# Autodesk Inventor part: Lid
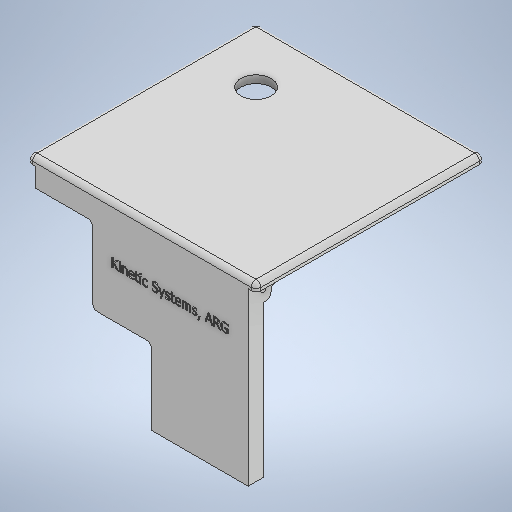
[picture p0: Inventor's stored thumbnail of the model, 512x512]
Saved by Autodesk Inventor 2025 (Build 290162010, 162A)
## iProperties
Created: 2023-12
Part Number: Lid
Material: Generic
Document SubType Name: Modeling
Designer: Andrew
Density: 1 g/cm^3
Appearance: Default
Author: Andrew
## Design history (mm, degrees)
sketch "Sketch1"
  geometry: L1 (76.2, 76.2)-(-76.2, 76.2); L2 (-76.2, 76.2)-(-76.2, -76.2); L3 (-76.2, -76.2)-(76.2, -76.2); L4 (76.2, -76.2)-(76.2, 76.2); 1 further point
  constraints: 8 end point, 2 parallel, 1 horizontal, 1 perpendicular
  dimensions: "d0" = 152.4 distance between parallel lines of L3 L1 (= d1); "d1" = 152.4 distance between parallel lines of L2 L4; "d2" = 76.2 distance from line of point (0, 0) L4 (= 0.5 x d1); "d3" = 76.2 distance from line of L3 point (0, 0) (= 0.5 x d1)
extrude "Extrusion1" new body sketch "Sketch1" distance "d4" = 5.08; taper "d5" = 0 deg
sketch "Sketch3"
  geometry: L1 (-76.2, 76.2)-(76.2, 76.2) reference; L2 (-70.993, 76.2)-(70.993, 76.2); L3 (70.993, 76.2)-(70.993, 71.12); L4 (70.993, 71.12)-(-70.993, 71.12); L5 (-70.993, 71.12)-(-70.993, 76.2); L6 (-76.2, -76.2)-(-76.2, 76.2) reference; L7 (76.2, 76.2)-(76.2, -76.2) reference; 2 further points
  constraints: 8 end point, 2 parallel, 1 horizontal, 1 perpendicular, 1 point on line
  dimensions: "d6" = 5.08 distance between parallel lines of L4 L1; "d7" = 5.207 distance between parallel lines of L6 L5; "d8" = 5.207 distance between parallel lines of L7 L3
extrude "Extrusion2" join sketch "Sketch3" distance "d9" = 76.2; taper "d10" = 0 deg
sketch "Sketch4"
  geometry: L1 (5.207, -5.08)-(5.207, -81.28) reference; L2 (5.207, -17.78)-(43.307, -17.78); L3 (43.307, -17.78)-(43.307, -81.28); L4 (43.307, -81.28)-(5.207, -81.28); L5 (5.207, -81.28)-(5.207, -17.78); L6 (147.193, -81.28)-(5.207, -81.28) reference; 2 further points
  constraints: 8 end point, 2 parallel, 1 horizontal, 1 perpendicular, 1 point on line
  dimensions: "d11" = 38.1 distance between parallel lines of L1 L3; "d12" = 63.5 distance between parallel lines of L4 L2; "d13" = 0 distance between parallel lines of L6 L4
extrude "Extrusion3" cut sketch "Sketch4" distance "d14" = 76.2; taper "d15" = 0 deg
sketch "Sketch5"
  geometry: L1 (-70.993, -70.993)-(70.993, -70.993); L2 (70.993, -70.993)-(70.993, -65.913); L3 (70.993, -65.913)-(-70.993, -65.913); L4 (-70.993, -65.913)-(-70.993, -70.993); L5 (70.993, -65.913)-(65.913, -65.913); L6 (65.913, -65.913)-(65.913, 71.12); L7 (65.913, 71.12)-(70.993, 71.12); L8 (70.993, 71.12)-(70.993, -65.913); L9 (-70.993, -65.913)-(-65.913, -65.913); L10 (-65.913, -65.913)-(-65.913, 71.12); L11 (-65.913, 71.12)-(-70.993, 71.12); L12 (-70.993, 71.12)-(-70.993, -65.913); L13 (76.2, -76.2)-(-76.2, -76.2) reference; L14 (-76.2, -76.2)-(-76.2, 76.2) reference; L15 (76.2, 76.2)-(76.2, -76.2) reference; L16 (70.993, 71.12)-(-70.993, 71.12) reference; 3 further points
  constraints: 24 end point, 6 parallel, 3 horizontal, 3 perpendicular, 1 point on line
  dimensions: "d16" = 5.08 distance between parallel lines of L1 L3; "d19" = 5.207 distance between parallel lines of L13 L1; "d20" = 5.207 distance between parallel lines of L14 L12 (= d19); "d21" = 5.207 distance between parallel lines of L15 L8 (= d19); "d22" = 5.08 distance between parallel lines of L8 L6 (= d16); "d23" = 5.08 distance between parallel lines of L10 L12 (= d16); "d24" = 0 distance between parallel lines of L16 L11
extrude "Extrusion4" join sketch "Sketch5" distance "d25" = 5.08; taper "d26" = 0 deg
sketch "Sketch6"
  geometry: L1 (5.08, 71.12)-(0, 71.12); L2 (0, 71.12)-(0, 0); L3 (0, 0)-(5.08, 0); L4 (5.08, 0)-(5.08, 71.12); L5 (136.906, 71.12)-(141.986, 71.12); L6 (141.986, 71.12)-(141.986, 63.5); L7 (141.986, 63.5)-(136.906, 63.5); L8 (136.906, 63.5)-(136.906, 71.12); L9 (103.886, 63.5)-(141.986, 63.5) reference; L10 (103.886, 0)-(0, 0) reference; 2 further points
  constraints: 16 end point, 4 parallel, 2 horizontal, 2 perpendicular, 1 midpoint
  dimensions: "d27" = 5.08 distance between parallel lines of L4 L2; "d28" = 5.08 distance between parallel lines of L6 L8; "d29" = 0 distance from line of L9 point (139.446, 63.5); "d30" = 0 distance between parallel lines of L10 L3
extrude "Extrusion5" join sketch "Sketch6" distance "d31" = 5.08; taper "d32" = 0 deg
fillet "Fillet1" dims "d33" = 3.175
fillet "Fillet9" dims "d140" = 6.35
sketch "Sketch7"
  geometry: L1 (-55.753, 60.96)-(-65.913, 60.96); L2 (-65.913, 60.96)-(-65.913, 71.12); L3 (-65.913, 71.12)-(-55.753, 71.12); L4 (-55.753, 71.12)-(-55.753, 60.96); L5 (55.753, 60.96)-(65.913, 60.96); L6 (65.913, 60.96)-(65.913, 71.12); L7 (65.913, 71.12)-(55.753, 71.12); L8 (55.753, 71.12)-(55.753, 60.96); L9 (-65.913, -62.738)-(-65.913, 62.865) reference; L10 (-36.068, 71.12)-(-62.738, 71.12) reference; L11 (65.913, 62.865)-(65.913, -62.738) reference; 2 further points
  constraints: 16 end point, 4 parallel, 2 horizontal, 2 perpendicular, 1 midpoint, 1 point on line
  dimensions: "d34" = 10.16 distance between parallel lines of L4 L2; "d35" = 10.16 distance between parallel lines of L1 L3; "d36" = 10.16 distance between parallel lines of L5 L7; "d37" = 10.16 distance from line of L6 point (55.753, 66.04); "d38" = 0 distance between parallel lines of L9 L2; "d39" = 0 distance between parallel lines of L10 L3; "d40" = 0 distance between parallel lines of L11 L6
extrude "Extrusion6" join sketch "Sketch7" distance "d41" = 12.7; taper "d42" = 0 deg
sketch "Sketch9"
  geometry: L1 (62.738, 60.96)-(55.753, 60.96) reference; L2 (70.993, 76.2)-(70.993, 66.04) reference; L3 (55.753, 60.96)-(70.993, 60.96); L4 (70.993, 60.96)-(70.993, 71.12); L5 (70.993, 71.12)-(55.753, 71.12); L6 (55.753, 71.12)-(55.753, 60.96); L7 (-55.753, 71.12)-(-55.753, 60.96) reference; L8 (-70.993, -64.643)-(-70.993, 76.2) reference; L9 (-55.753, 60.96)-(-70.993, 60.96); L10 (-70.993, 60.96)-(-70.993, 71.12); L11 (-70.993, 71.12)-(-55.753, 71.12); L12 (-55.753, 71.12)-(-55.753, 60.96); 7 further points
  constraints: 16 end point, 4 parallel, 2 horizontal, 2 perpendicular, 2 point on line, 1 midpoint
extrude "Extrusion8" join sketch "Sketch9" stored distance "d49" = 25.4; taper "d50" = 0 deg
sketch "Sketch8"
  geometry: L1 (-3.175, 17.78)-(-149.225, 17.78) reference; L2 (0, 12.7)-(0, 0) reference; L3 (-149.225, 12.7)-(-3.175, 12.7) reference; C1 r 1.905 at (-10.16, 7.62); 1 further point
  constraints: 1 centre point
  dimensions: "d43" = 3.81 diameter of C1; "d45" = 10.16 distance from line of L2 C1.centre; "d48" = 5.08 distance from line of L3 C1.centre
extrude "Extrusion7" cut sketch "Sketch8" extent not by distance; stored distance "d46" = 0; taper "d47" = 0 deg
fillet "Fillet2" dims "d51" = 3.175
sketch "Sketch10"
  geometry: L1 (3.489, 7.188)-(5.073, 4.445); L2 (5.073, 4.445)-(3.489, 1.702); L3 (3.489, 1.702)-(0.321, 1.702); L4 (0.321, 1.702)-(-1.263, 4.445); L5 (-1.263, 4.445)-(0.321, 7.188); L6 (0.321, 7.188)-(3.489, 7.188); C1 r 1.905 at (1.905, 4.445) reference; 2 further points
  constraints: 12 end point, 1 coincident, 1 horizontal, 13 other
  dimensions: "d52" = 5.4864 distance between parallel lines of L1 L4
extrude "Extrusion9" cut sketch "Sketch10" stored distance "d53" = 7.62; taper "d54" = 0 deg
sketch "Sketch11"
  geometry: L1 (-0.321, 7.188)-(-3.489, 7.188) reference; L2 (-0.321, 7.188)-(1.263, 4.445); L3 (1.263, 4.445)-(-0.321, 1.702); L4 (-0.321, 1.702)-(-3.489, 1.702); L5 (-3.489, 1.702)-(-5.073, 4.445); L6 (-5.073, 4.445)-(-3.489, 7.188); L7 (-3.489, 7.188)-(-0.321, 7.188); C1 r 1.905 at (-1.905, 4.445) reference; 3 further points
  constraints: 12 end point, 1 coincident, 13 other
extrude "Extrusion10" cut sketch "Sketch11" stored distance "d55" = 7.62; taper "d56" = 0 deg
sketch "Sketch12"
  geometry: L1 (64.643, -70.993)-(-64.643, -70.993) reference; L2 (-7.62, -70.993)-(7.62, -70.993); L3 (7.62, -70.993)-(7.62, -55.753); L4 (7.62, -55.753)-(-7.62, -55.753); L5 (-7.62, -55.753)-(-7.62, -70.993); 4 further points
  constraints: 8 end point, 2 parallel, 1 horizontal, 1 perpendicular, 1 point on line
  dimensions: "d57" = 15.24 distance between parallel lines of L3 L5; "d58" = 15.24 distance between parallel lines of L1 L4; "d59" = 7.62 distance from line of point (0, 0) L5 (= 0.5 x d57)
extrude "Extrusion11" join sketch "Sketch12" distance "d60" = 12.7; taper "d61" = 0 deg
fillet "Fillet3" dims "d62" = 3.175
sketch "Sketch25"
  geometry: L1 (72.263, -8.255)-(72.263, -9.525) reference; L2 (-8.382, 0)-(137.668, 0) reference; C1 r 1.905 at (64.643, -5.08); 2 further points
  constraints: 1 centre point, 1 midpoint
  dimensions: "d144" = 7.62 horizontal distance of C1.centre point (72.263, -8.89); "d145" = 5.08 distance from line of L2 C1.centre; "d146" = 3.81 diameter of C1
sketch "Sketch14"
  geometry: L1 (3.297, 1.65)-(1.713, 4.393); L2 (1.713, 4.393)-(3.297, 7.137); L3 (3.297, 7.137)-(6.464, 7.137); L4 (6.464, 7.137)-(8.048, 4.393); L5 (8.048, 4.393)-(6.464, 1.65); L6 (6.464, 1.65)-(3.297, 1.65); 4 further points
  constraints: 12 end point, 1 coincident, 1 horizontal, 14 other
  dimensions: "d68" = 5.4864 distance between parallel lines of L4 L1
extrude "Extrusion13" cut sketch "Sketch14" distance "d69" = 7.62; taper "d70" = 0 deg
extrude "Extrusion23" cut sketch "Sketch25" distance "d147" = 19.05; taper "d148" = 0 deg
sketch "Sketch15"
  geometry: L1 (-76.2, 73.025)-(-76.2, -73.025) reference; L2 (-73.025, -76.2)-(73.025, -76.2) reference; L3 (73.025, 76.2)-(-73.025, 76.2) reference; C1 r 10.16 at (-38.1, 38.1); 1 further point
  constraints: 1 centre point
  dimensions: "d71" = 20.32 diameter of C1; "d72" = 38.1 distance from line of C1.centre L1; "d73" = 152.4 distance between parallel lines of L2 L3 (derived); "d74" = 38.1 distance from line of C1.centre L3 (= 0.25 x d73)
extrude "Extrusion14" cut sketch "Sketch15" distance "d75" = 25.4; taper "d76" = 0 deg
sketch "Sketch16"
  geometry: L1 (-32.893, 76.2)-(-32.893, 71.12) reference; L2 (-32.893, 71.12)-(62.738, 71.12) reference; L3 (65.913, 67.945)-(65.913, 66.04) reference; L4 (70.993, 66.04)-(65.913, 66.04) reference; L5 (70.993, 76.2)-(70.993, 66.04) reference; L6 (70.993, 76.2)-(-32.893, 76.2) reference; L7 (6.477, 76.2)-(6.477, 71.12); A1 r 3.175 centre (62.738, 67.945) between (65.913, 67.945) and (62.738, 71.12) reference; 3 further points
  constraints: 2 end point, 2 midpoint, 2 point on line, 1 perpendicular
  dimensions: "d77" = 39.37 distance of point (-32.893, 73.66) point (6.477, 73.66)
extrude "Extrusion15" join sketch "Sketch16" distance "d78" = 37.846; taper "d79" = 0 deg
sketch "Sketch17"
  geometry: L1 (6.477, 71.12)-(6.477, 76.2) reference; L2 (6.477, 76.2)-(-32.893, 76.2) reference; L3 (-32.893, 76.2)-(-32.893, 71.12) reference; L4 (-32.893, 71.12)-(6.477, 71.12) reference; 1 further point
extrude "Extrusion16" cut sketch "Sketch17" distance "d81" = 12.7; taper "d82" = 0 deg
fillet "Fillet4" dims "d80" = 3.175
sketch "Sketch23"
  geometry: L1 (-12.7, 58.42)-(0, 58.42); L2 (0, 58.42)-(0, 71.12); L3 (0, 71.12)-(-12.7, 71.12); L4 (-12.7, 71.12)-(-12.7, 58.42); L5 (0, 57.785)-(0, -62.738) reference; L6 (-114.046, 71.12)-(-15.875, 71.12) reference; A1 r 10.16 centre (-9.71, 61.41) between (0, 58.42) and (-12.7, 71.12); 4 further points
  constraints: 8 end point, 2 parallel, 2 point on circle, 1 centre point, 1 horizontal, 1 midpoint, 1 perpendicular
  dimensions: "d121" = 0 distance from line of L5 point (0, 64.77); "d122" = 0 distance between parallel lines of L6 L3; "d123" = 12.7 distance of L3.end L1.start; "d124" = 12.7 distance of L1.start L1.end; "d125" = 10.16 radius of A1
extrude "Extrusion21" join sketch "Sketch23" stored distance "d126" = 111.4044; taper "d127" = 0 deg
sketch "Sketch18"
  geometry: L1 (5.08, -65.913)-(-5.08, -65.913); L2 (-5.08, -65.913)-(-5.08, 71.12); L3 (-5.08, 71.12)-(5.08, 71.12); L4 (5.08, 71.12)-(5.08, -65.913); L5 (65.913, -5.08)-(-65.913, -5.08); L6 (-65.913, -5.08)-(-65.913, 5.08); L7 (-65.913, 5.08)-(65.913, 5.08); L8 (65.913, 5.08)-(65.913, -5.08); L9 (3.302, 71.12)-(-29.718, 71.12) reference; L10 (-10.795, -65.913)-(-62.738, -65.913) reference; L11 (-65.913, -62.738)-(-65.913, 57.785) reference; L12 (65.913, 57.785)-(65.913, -62.738) reference; 3 further points
  constraints: 16 end point, 4 collinear, 4 parallel, 2 horizontal, 2 perpendicular
  dimensions: "d83" = 10.16 distance between parallel lines of L7 L5; "d84" = 10.16 distance between parallel lines of L2 L4; "d85" = 5.08 distance from line of point (0, 0) L5 (= 0.5 x d83); "d86" = 5.08 distance from line of point (0, 0) L4 (= 0.5 x d84)
extrude "Extrusion17" join sketch "Sketch18" distance "d87" = 3.81; taper "d88" = 0 deg
fillet "Fillet5" dims "d89" = 3.175
sketch "Sketch19"
  geometry: L1 (-48.895, 12.7)-(-48.895, -101.346); L2 (-48.895, -101.346)-(-59.055, -101.346); L3 (-59.055, -101.346)-(-59.055, 12.7); L4 (-42.545, -101.346)-(-98.806, -101.346) reference; L5 (-42.545, -101.346)-(-42.545, -53.975) reference; L6 (-101.981, -13.97)-(-3.175, -13.97); L7 (-3.175, -13.97)-(-3.175, -24.13); L8 (-3.175, -24.13)-(-101.981, -24.13); L9 (-101.981, -24.13)-(-101.981, -13.97); L10 (-101.981, -3.175)-(-101.981, -101.346) reference; L11 (-3.175, -47.625)-(-3.175, -3.175) reference; L12 (-39.37, -50.8)-(-6.35, -50.8) reference; L13 (16.51, 12.7)-(-27.813, 12.7) reference; L14 (-27.813, 12.7)-(16.51, 12.7) reference; L15 (-59.055, 12.7)-(-48.895, 12.7); 6 further points
  constraints: 16 end point, 3 collinear, 3 parallel, 2 horizontal, 2 midpoint, 1 perpendicular
  dimensions: "d90" = 10.16 distance from line of point (-48.895, -44.323) L3; "d91" = 6.35 distance between parallel lines of L5 L1; "d97" = 10.16 distance between parallel lines of L8 L6; "d128" = 31.75 distance from line of L14 point (-3.175, -19.05); "d129" = 0 distance between parallel lines of L14 L15
extrude "Extrusion18" join sketch "Sketch19" distance "d92" = 3.81; taper "d93" = 0 deg
chamfer "Chamfer1" distance "d94" = 3.81; stored, may be unused: second distance "d95" = 3.175, angle "d96" = 45 deg
sketch "Sketch20"
  geometry: L1 (29.147, -65.913)-(44.387, -65.913); L2 (44.387, -65.913)-(44.386, -2.435); L3 (44.386, -2.435)-(29.146, -2.435); L4 (29.146, -2.435)-(29.147, -65.913); L5 (62.738, -65.913)-(10.795, -65.913) reference; L6 (62.738, -2.435)-(-62.738, -2.435) reference; L7 (65.913, 57.785)-(65.913, -62.738) reference; L8 (7.62, -58.928)-(7.62, -62.738) reference; L9 (-44.387, -65.913)-(-29.147, -65.913); L10 (-29.147, -65.913)-(-29.147, -2.435); L11 (-29.147, -2.435)-(-44.387, -2.435); L12 (-44.387, -2.435)-(-44.387, -65.913); L13 (-65.913, -62.738)-(-65.913, 57.785) reference; L14 (-10.795, -65.913)-(-62.738, -65.913) reference; C1 r 10.16 at (-38.1, -38.1) reference; C2 r 22.86 at (-38.1, -38.1); C3 r 17.78 at (-38.1, -38.1); 11 further points
  constraints: 16 end point, 4 collinear, 4 midpoint, 4 parallel, 2 centre point, 2 coincident, 2 horizontal, 2 perpendicular
  dimensions: "d101" = 15.24 distance between parallel lines of L2 L4; "d102" = 58.293 distance from line of L7 point (7.62, -60.833) (derived); "d103" = 29.1465 distance from line of L7 point (36.767, -65.913) (= 0.5 x d102); "d104" = 15.24 distance from line of point (-29.147, -34.174) L12 (= d101); "d105" = 29.1465 distance from line of point (-36.767, -2.435) L13 (= d103); "d106" = 12.7 radial gap between concentric circles of C1 C2; "d149" = 35.56 diameter of C3
extrude "Extrusion19" join sketch "Sketch20" distance "d107" = 3.81; taper "d108" = 0 deg
fillet "Fillet6" dims "d112" = 3.81
sketch "Sketch24"
  geometry: L1 (-31.75, 39.37)-(0, 39.37); L2 (0, 39.37)-(0, 71.12); L3 (0, 71.12)-(-31.75, 71.12); L4 (-31.75, 71.12)-(-31.75, 39.37); L5 (0, 64.4)-(0, 8.255) reference; L6 (-6.72, 71.12)-(-26.67, 71.12) reference; A1 r 50.8 centre (-48.098, 23.022) between (0, 39.37) and (-31.75, 71.12); 1 further point
  constraints: 8 end point, 2 parallel, 2 point on circle, 1 centre point, 1 horizontal, 1 perpendicular
  dimensions: "d130" = 31.75 distance of L1.end L2.end; "d131" = 31.75 distance of L2.end L3.end; "d132" = 0 distance between parallel lines of L5 L2; "d133" = 0 distance between parallel lines of L6 L3; "d134" = 50.8 radius of A1
extrude "Extrusion22" join sketch "Sketch24" distance "d135" = 19.05; taper "d137" = 0 deg; dims "d136" = 5.1054, "d138" = 0
fillet "Fillet8" dims "d139" = 3.175
sketch "Sketch27"
  geometry: L1 (50.283, -14.161)-(129.803, -14.161); L2 (129.803, -14.161)-(129.803, -22.034); L3 (129.803, -22.034)-(50.283, -22.034); L4 (50.283, -22.034)-(50.283, -14.161); L5 (141.986, 12.7)-(141.986, -101.346) reference; L6 (38.1, -3.175)-(38.1, -47.625) reference; L7 (41.275, -50.8)-(74.295, -50.8) reference; L8 (-2.032, 14.605)-(144.018, 14.605) reference; 3 further points
  constraints: 2 midpoint, 2 other
  dimensions: "d150" = 103.886 distance between parallel lines of L5 L6 (derived); "d151" = 51.943 distance from line of point (90.043, -14.161) L6 (derived); "d152" = 65.405 distance between parallel lines of L7 L8 (derived); "d153" = 32.7025 distance from line of point (50.283, -18.098) L8 (derived)
extrude "Extrusion24" cut sketch "Sketch27" distance "d154" = 0.508; taper "d155" = 0 deg
body "Solid1"
node "Projected Loop1"
node "Projected Loop2"
